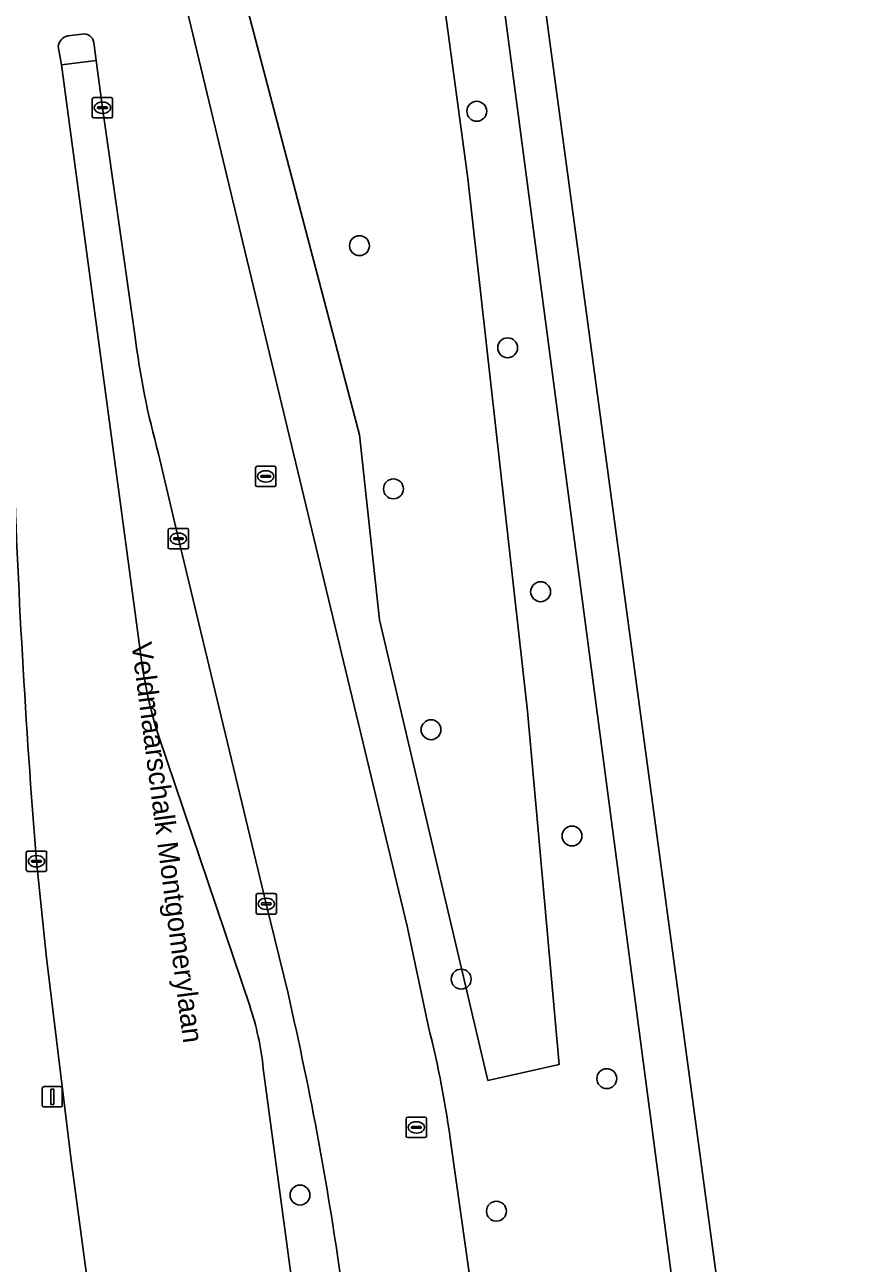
# Model space of a CAD drawing. Extents: x 160554 to 161248, y 385329 to 386506.
# Drawn here: x 161206.1 to 161247.5, y 385410.6 to 385471.5 of the extents above; entities that cross this region are included whole.
import ezdxf

# ---------------------------------------------------------------- set-up
doc = ezdxf.new("R2010")
doc.units = 0
for name, color, linetype in [('IMGEO_Berm_groen', 7, 'Continuous'), ('IMGEO_Boom', 7, 'Continuous'), ('IMGEO_Kolk', 7, 'Continuous'), ('IMGEO_Lichtmast', 7, 'Continuous'), ('IMGEO_Openbare_ruimte_label', 7, 'Continuous'), ('IMGEO_OVBaan_gesloten', 7, 'Continuous'), ('IMGEO_Rijbaan_regionaal_gesloten', 7, 'Continuous'), ('IMGEO_Rioolput', 7, 'Continuous'), ('IMGEO_Verkeerseiland_gesloten', 7, 'Continuous')]:
    doc.layers.add(name, color=color, linetype=linetype)

msp = doc.modelspace()

# ---------------------------------------------------------------- linework, layer by layer
at = {"layer": 'IMGEO_Berm_groen'}
for points in [[(161242.98, 385371.343), (161241.544, 385382.082), (161219.183, 385551.578)], [(161210.311, 385487.611), (161214.026, 385472.285), (161220.183, 385446.691), (161224.858, 385427.207), (161225.91, 385422.267)], [(161211.476, 385456.268), (161209.882, 385467.439), (161209.567, 385469.769), (161207.865, 385469.556), (161209.629, 385456.485), (161211.754, 385440.641)], [(161219.005, 385423.892), (161217.938, 385428.306), (161213.613, 385446.254), (161212.64, 385450.42)], [(161212.631, 385436.585), (161217.122, 385423.299)], [(161214.499, 385369.533), (161214.446, 385369.859), (161213.175, 385379.682), (161208.341, 385415.704), (161207.134, 385425.648), (161206.638, 385430.4)], [(161217.791, 385420.215), (161220.192, 385402.355), (161222.261, 385386.454), (161224.454, 385370.254)], [(161227.022, 385416.43), (161229.12, 385401.59), (161231.052, 385387.767), (161233.273, 385371.686), (161233.441, 385370.622)]]:
    msp.add_lwpolyline(points, dxfattribs=at)
for points in [[(161232.33, 385420.404), (161230.78, 385437.781), (161227.84, 385463.955), (161224.569, 385488.214), (161222.744, 385492.021), (161218.845, 385492.028), (161213.502, 385487.327), (161213.356, 385482.588), (161216.318, 385474.919), (161222.515, 385451.366), (161223.505, 385442.268), (161228.835, 385419.625)], [(161218.845, 385492.028), (161222.744, 385492.021), (161224.569, 385488.214), (161227.84, 385463.955), (161230.78, 385437.781), (161232.33, 385420.404), (161228.835, 385419.625), (161223.505, 385442.268), (161222.515, 385451.366), (161216.318, 385474.919), (161213.356, 385482.588), (161213.502, 385487.327)]]:
    msp.add_lwpolyline(points, close=True, dxfattribs=at)
for centre, radius, start, end in [((161251.907, 385461.276), 40.739, 187.06044, 195.45389), ((161634.192, 385464.788), 428.934, 181.89143, 184.59841), ((161232.926, 385443.096), 21.314, 186.6144, 197.78726), ((161056.364, 385386.475), 166.89, 7.8166, 12.9561), ((161203.141, 385418.652), 14.733, 6.09126, 18.38738), ((161177.607, 385410.04), 49.827, 7.36774, 14.20446)]:
    msp.add_arc(centre, radius, start, end, dxfattribs=at)
at = {"layer": 'IMGEO_Boom'}
for centre in [(161228.285, 385467.266), (161222.517, 385460.658), (161229.803, 385455.641), (161224.188, 385448.703), (161231.424, 385443.648), (161226.037, 385436.864), (161232.969, 385431.642), (161227.52, 385424.604), (161234.678, 385419.714), (161219.594, 385413.99), (161229.252, 385413.196)]:
    msp.add_circle(centre, 0.489, dxfattribs=at)
at = {"layer": 'IMGEO_Kolk'}
for p, q in [((161209.381, 385467.013), (161209.381, 385467.865)), ((161209.456, 385467.939), (161210.308, 385467.939)), ((161209.683, 385467.482), (161210.081, 385467.482)), ((161209.869, 385467.719), (161209.894, 385467.719)), ((161210.382, 385467.865), (161210.382, 385467.013)), ((161210.308, 385466.939), (161209.456, 385466.939)), ((161209.64, 385467.433), (161209.64, 385467.445)), ((161210.078, 385467.396), (161209.68, 385467.396)), ((161209.892, 385467.159), (161209.867, 385467.159)), ((161210.124, 385467.445), (161210.124, 385467.433)), ((161213.112, 385445.828), (161213.112, 385446.68)), ((161213.187, 385446.754), (161214.039, 385446.754)), ((161213.371, 385446.248), (161213.371, 385446.26)), ((161213.809, 385446.211), (161213.411, 385446.211)), ((161213.414, 385446.297), (161213.812, 385446.297)), ((161213.6, 385446.534), (161213.625, 385446.534)), ((161213.855, 385446.26), (161213.855, 385446.248)), ((161214.113, 385446.68), (161214.113, 385445.828)), ((161214.039, 385445.754), (161213.187, 385445.754)), ((161213.623, 385445.974), (161213.598, 385445.974)), ((161206.137, 385429.974), (161206.137, 385430.826)), ((161206.212, 385430.9), (161207.064, 385430.9)), ((161206.396, 385430.394), (161206.396, 385430.406)), ((161206.834, 385430.357), (161206.436, 385430.357)), ((161206.439, 385430.443), (161206.837, 385430.443)), ((161206.625, 385430.68), (161206.65, 385430.68)), ((161206.88, 385430.406), (161206.88, 385430.394)), ((161207.138, 385430.826), (161207.138, 385429.974)), ((161207.064, 385429.9), (161206.212, 385429.9)), ((161206.648, 385430.12), (161206.623, 385430.12)), ((161217.437, 385427.88), (161217.437, 385428.732)), ((161217.512, 385428.806), (161218.364, 385428.806)), ((161217.925, 385428.586), (161217.95, 385428.586)), ((161218.438, 385428.732), (161218.438, 385427.88)), ((161217.696, 385428.3), (161217.696, 385428.312)), ((161218.134, 385428.263), (161217.736, 385428.263)), ((161217.739, 385428.349), (161218.137, 385428.349)), ((161217.948, 385428.026), (161217.923, 385428.026)), ((161218.18, 385428.312), (161218.18, 385428.3)), ((161218.364, 385427.806), (161217.512, 385427.806))]:
    msp.add_line(p, q, dxfattribs=at)
for points in [[(161209.381, 385467.013), (161209.381, 385467.865)], [(161209.456, 385467.939), (161210.308, 385467.939)], [(161210.382, 385467.865), (161210.382, 385467.013)], [(161210.308, 385466.939), (161209.456, 385466.939)], [(161213.112, 385445.828), (161213.112, 385446.68)], [(161213.187, 385446.754), (161214.039, 385446.754)], [(161214.113, 385446.68), (161214.113, 385445.828)], [(161214.039, 385445.754), (161213.187, 385445.754)], [(161206.137, 385429.974), (161206.137, 385430.826)], [(161206.212, 385430.9), (161207.064, 385430.9)], [(161207.138, 385430.826), (161207.138, 385429.974)], [(161207.064, 385429.9), (161206.212, 385429.9)], [(161217.437, 385427.88), (161217.437, 385428.732)], [(161217.512, 385428.806), (161218.364, 385428.806)], [(161218.438, 385428.732), (161218.438, 385427.88)], [(161218.364, 385427.806), (161217.512, 385427.806)]]:
    msp.add_lwpolyline(points, dxfattribs=at)
for centre, radius, start, end in [((161209.458, 385467.863), 0.0765, 91.55205, 178.44795), ((161209.458, 385467.863), 0.0765, 91.55205, 178.44795), ((161209.68, 385467.442), 0.0403, 85.87752, 175.75265), ((161210.085, 385467.444), 0.0386, 1.73085, 96.63898), ((161210.306, 385467.863), 0.0765, 1.55205, 88.44795), ((161210.306, 385467.863), 0.0765, 1.55205, 88.44795), ((161209.458, 385467.015), 0.0765, 181.55205, 268.44795), ((161209.458, 385467.015), 0.0765, 181.55205, 268.44795), ((161209.677, 385467.432), 0.0366, 178.93798, 274.71019), ((161210.081, 385467.439), 0.043, 264.86636, 352.45326), ((161210.306, 385467.015), 0.0765, 271.55205, 358.44795), ((161210.306, 385467.015), 0.0765, 271.55205, 358.44795), ((161213.189, 385446.678), 0.0765, 91.55205, 178.44795), ((161213.189, 385446.678), 0.0765, 91.55205, 178.44795), ((161213.411, 385446.257), 0.0403, 85.87752, 175.75265), ((161213.408, 385446.247), 0.0366, 178.93798, 274.71019), ((161213.812, 385446.254), 0.043, 264.86636, 352.45326), ((161213.816, 385446.259), 0.0386, 1.73085, 96.63898), ((161214.037, 385446.678), 0.0765, 1.55205, 88.44795), ((161214.037, 385446.678), 0.0765, 1.55205, 88.44795), ((161213.189, 385445.83), 0.0765, 181.55205, 268.44795), ((161213.189, 385445.83), 0.0765, 181.55205, 268.44795), ((161214.037, 385445.83), 0.0765, 271.55205, 358.44795), ((161214.037, 385445.83), 0.0765, 271.55205, 358.44795), ((161206.214, 385430.824), 0.0765, 91.55205, 178.44795), ((161206.214, 385430.824), 0.0765, 91.55205, 178.44795), ((161206.436, 385430.403), 0.0403, 85.87752, 175.75265), ((161206.433, 385430.393), 0.0366, 178.93798, 274.71019), ((161206.837, 385430.4), 0.043, 264.86636, 352.45326), ((161206.841, 385430.405), 0.0386, 1.73085, 96.63898), ((161207.062, 385430.824), 0.0765, 1.55205, 88.44795), ((161207.062, 385430.824), 0.0765, 1.55205, 88.44795), ((161206.214, 385429.976), 0.0765, 181.55205, 268.44795), ((161206.214, 385429.976), 0.0765, 181.55205, 268.44795), ((161207.062, 385429.976), 0.0765, 271.55205, 358.44795), ((161207.062, 385429.976), 0.0765, 271.55205, 358.44795), ((161217.514, 385428.73), 0.0765, 91.55205, 178.44795), ((161217.514, 385428.73), 0.0765, 91.55205, 178.44795), ((161218.362, 385428.73), 0.0765, 1.55205, 88.44795), ((161218.362, 385428.73), 0.0765, 1.55205, 88.44795), ((161217.736, 385428.309), 0.0403, 85.87752, 175.75265), ((161217.733, 385428.299), 0.0366, 178.93798, 274.71019), ((161218.137, 385428.306), 0.043, 264.86636, 352.45326), ((161218.141, 385428.311), 0.0386, 1.73085, 96.63898), ((161217.514, 385427.882), 0.0765, 181.55205, 268.44795), ((161217.514, 385427.882), 0.0765, 181.55205, 268.44795), ((161218.362, 385427.882), 0.0765, 271.55205, 358.44795), ((161218.362, 385427.882), 0.0765, 271.55205, 358.44795)]:
    msp.add_arc(centre, radius, start, end, dxfattribs=at)
for centre, major_axis, ratio, start_param, end_param in [((161209.868, 385467.439), (-0.387, 0.002), 0.722429, 4.712389, 7.853982), ((161209.893, 385467.439), (-0.39, 0.002), 0.717154, 1.570796, 4.712389), ((161213.599, 385446.254), (-0.387, 0.002), 0.722429, 4.712389, 7.853982), ((161213.624, 385446.254), (-0.39, 0.002), 0.717154, 1.570796, 4.712389), ((161206.624, 385430.4), (-0.387, 0.002), 0.722429, 4.712389, 7.853982), ((161206.649, 385430.4), (-0.39, 0.002), 0.717154, 1.570796, 4.712389), ((161217.924, 385428.306), (-0.387, 0.002), 0.722429, 4.712389, 7.853982), ((161217.949, 385428.306), (-0.39, 0.002), 0.717154, 1.570796, 4.712389)]:
    msp.add_ellipse(centre, major_axis=major_axis, ratio=ratio, start_param=start_param, end_param=end_param, dxfattribs=at)
at = {"layer": 'IMGEO_Lichtmast'}
for p, q in [((161206.917, 385418.422), (161206.917, 385419.222)), ((161206.917, 385419.222), (161206.917, 385418.422)), ((161207.017, 385419.322), (161207.807, 385419.322)), ((161207.807, 385419.322), (161207.017, 385419.322)), ((161207.907, 385419.222), (161207.907, 385418.422)), ((161207.907, 385418.422), (161207.907, 385419.222)), ((161207.807, 385418.322), (161207.017, 385418.322)), ((161207.017, 385418.322), (161207.807, 385418.322))]:
    msp.add_line(p, q, dxfattribs=at)
msp.add_lwpolyline([(161207.337, 385419.197), (161207.487, 385419.197), (161207.487, 385418.447), (161207.337, 385418.447), (161207.337, 385419.197)], dxfattribs=at)
for centre, start, end in [((161207.017, 385419.222), 90, 180), ((161207.017, 385419.222), 90, 180), ((161207.807, 385419.222), 0, 90), ((161207.807, 385419.222), 360, 90), ((161207.017, 385418.422), 180, 270), ((161207.017, 385418.422), 180, 270), ((161207.807, 385418.422), 270, 0), ((161207.807, 385418.422), 270, 0)]:
    msp.add_arc(centre, 0.1, start, end, dxfattribs=at)
at = {"layer": 'IMGEO_OVBaan_gesloten'}
msp.add_lwpolyline([(161247.533, 385354.716), (161220.927, 385551.802), (161219.183, 385551.578), (161241.544, 385382.082), (161242.98, 385371.343), (161243.331, 385368.659), (161243.758, 385365.555), (161244.71, 385357.846), (161245.105, 385354.451)], close=True, dxfattribs=at)
at = {"layer": 'IMGEO_Rijbaan_regionaal_gesloten'}
for points in [[(161225.91, 385422.267), (161224.858, 385427.207), (161220.183, 385446.691), (161214.026, 385472.285), (161210.311, 385487.611)], [(161208.181, 385470.97), (161208.886, 385471.062)], [(161209.458, 385470.653), (161209.475, 385470.512), (161209.567, 385469.769), (161209.882, 385467.439), (161211.476, 385456.268)], [(161211.754, 385440.641), (161209.629, 385456.485), (161207.865, 385469.556), (161207.699, 385470.444)], [(161212.64, 385450.42), (161213.613, 385446.254), (161217.938, 385428.306)], [(161217.122, 385423.299), (161212.631, 385436.585)], [(161206.638, 385430.4), (161207.134, 385425.648), (161208.341, 385415.704), (161213.175, 385379.682), (161214.446, 385369.859), (161214.499, 385369.533), (161214.699, 385366.887)], [(161217.938, 385428.306), (161219.005, 385423.892)], [(161225.407, 385362.981), (161225.153, 385364.369), (161224.777, 385367.541), (161224.454, 385370.254), (161222.261, 385386.454), (161220.192, 385402.355), (161217.791, 385420.215)], [(161235.082, 385364.529), (161235.029, 385364.779), (161234.982, 385364.995), (161234.074, 385368.098), (161233.441, 385370.622), (161233.273, 385371.686), (161231.052, 385387.767), (161229.12, 385401.59), (161227.022, 385416.43)]]:
    msp.add_lwpolyline(points, dxfattribs=at)
for centre, radius, start, end in [((161208.309, 385470.369), 0.614, 101.99836, 173.00048), ((161208.968, 385470.573), 0.496, 9.29489, 99.57293), ((161251.907, 385461.276), 40.739, 187.06044, 195.45389), ((161634.192, 385464.788), 428.934, 181.89143, 184.59841), ((161232.926, 385443.096), 21.314, 186.6144, 197.78726), ((161056.364, 385386.475), 166.89, 7.8166, 12.9561), ((161203.141, 385418.652), 14.733, 6.09126, 18.38738), ((161177.607, 385410.04), 49.827, 7.36774, 14.20446)]:
    msp.add_arc(centre, radius, start, end, dxfattribs=at)
at = {"layer": 'IMGEO_Rioolput'}
for p, q in [((161217.409, 385448.891), (161217.409, 385449.743)), ((161217.484, 385449.817), (161218.336, 385449.817)), ((161217.668, 385449.311), (161217.668, 385449.323)), ((161218.106, 385449.274), (161217.708, 385449.274)), ((161217.711, 385449.36), (161218.109, 385449.36)), ((161217.897, 385449.597), (161217.922, 385449.597)), ((161218.152, 385449.323), (161218.152, 385449.311)), ((161218.41, 385449.743), (161218.41, 385448.891)), ((161218.336, 385448.817), (161217.484, 385448.817)), ((161217.92, 385449.037), (161217.895, 385449.037)), ((161224.813, 385416.891), (161224.813, 385417.743)), ((161224.888, 385417.817), (161225.74, 385417.817)), ((161225.301, 385417.597), (161225.326, 385417.597)), ((161225.814, 385417.743), (161225.814, 385416.891)), ((161225.072, 385417.311), (161225.072, 385417.323)), ((161225.51, 385417.274), (161225.112, 385417.274)), ((161225.115, 385417.36), (161225.513, 385417.36)), ((161225.324, 385417.037), (161225.299, 385417.037)), ((161225.556, 385417.323), (161225.556, 385417.311)), ((161225.74, 385416.817), (161224.888, 385416.817))]:
    msp.add_line(p, q, dxfattribs=at)
for points in [[(161217.409, 385448.891), (161217.409, 385449.743)], [(161217.484, 385449.817), (161218.336, 385449.817)], [(161218.41, 385449.743), (161218.41, 385448.891)], [(161218.336, 385448.817), (161217.484, 385448.817)], [(161224.813, 385416.891), (161224.813, 385417.743)], [(161224.888, 385417.817), (161225.74, 385417.817)], [(161225.814, 385417.743), (161225.814, 385416.891)], [(161225.74, 385416.817), (161224.888, 385416.817)]]:
    msp.add_lwpolyline(points, dxfattribs=at)
for centre, radius, start, end in [((161217.486, 385449.741), 0.0765, 91.55205, 178.44795), ((161217.486, 385449.741), 0.0765, 91.55205, 178.44795), ((161217.708, 385449.32), 0.0403, 85.87752, 175.75265), ((161217.705, 385449.31), 0.0366, 178.93798, 274.71019), ((161218.109, 385449.317), 0.043, 264.86636, 352.45326), ((161218.113, 385449.322), 0.0386, 1.73085, 96.63898), ((161218.334, 385449.741), 0.0765, 1.55205, 88.44795), ((161218.334, 385449.741), 0.0765, 1.55205, 88.44795), ((161217.486, 385448.893), 0.0765, 181.55205, 268.44795), ((161217.486, 385448.893), 0.0765, 181.55205, 268.44795), ((161218.334, 385448.893), 0.0765, 271.55205, 358.44795), ((161218.334, 385448.893), 0.0765, 271.55205, 358.44795), ((161224.89, 385417.741), 0.0765, 91.55205, 178.44795), ((161224.89, 385417.741), 0.0765, 91.55205, 178.44795), ((161225.738, 385417.741), 0.0765, 1.55205, 88.44795), ((161225.738, 385417.741), 0.0765, 1.55205, 88.44795), ((161225.112, 385417.32), 0.0403, 85.87752, 175.75265), ((161225.109, 385417.31), 0.0366, 178.93798, 274.71019), ((161225.513, 385417.317), 0.043, 264.86636, 352.45326), ((161225.517, 385417.322), 0.0386, 1.73085, 96.63898), ((161224.89, 385416.893), 0.0765, 181.55205, 268.44795), ((161224.89, 385416.893), 0.0765, 181.55205, 268.44795), ((161225.738, 385416.893), 0.0765, 271.55205, 358.44795), ((161225.738, 385416.893), 0.0765, 271.55205, 358.44795)]:
    msp.add_arc(centre, radius, start, end, dxfattribs=at)
for centre, major_axis, ratio, start_param, end_param in [((161217.896, 385449.317), (-0.387, 0.002), 0.722429, 4.712389, 7.853982), ((161217.921, 385449.317), (-0.39, 0.002), 0.717154, 1.570796, 4.712389), ((161225.3, 385417.317), (-0.387, 0.002), 0.722429, 4.712389, 7.853982), ((161225.325, 385417.317), (-0.39, 0.002), 0.717154, 1.570796, 4.712389)]:
    msp.add_ellipse(centre, major_axis=major_axis, ratio=ratio, start_param=start_param, end_param=end_param, dxfattribs=at)
at = {"layer": 'IMGEO_Verkeerseiland_gesloten'}
for points in [[(161208.886, 385471.062), (161208.181, 385470.97)], [(161209.475, 385470.512), (161209.458, 385470.653)], [(161207.699, 385470.444), (161207.865, 385469.556), (161209.567, 385469.769), (161209.475, 385470.512)]]:
    msp.add_lwpolyline(points, dxfattribs=at)
for centre, radius, start, end in [((161208.309, 385470.369), 0.614, 101.99836, 173.00048), ((161208.968, 385470.573), 0.496, 9.29489, 99.57293)]:
    msp.add_arc(centre, radius, start, end, dxfattribs=at)

# ---------------------------------------------------------------- texts
at = {"layer": 'IMGEO_Openbare_ruimte_label'}
msp.add_text('Veldmaarschalk Montgomerylaan', height=1, rotation=277.40918, dxfattribs=at).set_placement((161211.303, 385441.101))

doc.saveas('drawing.dxf')
